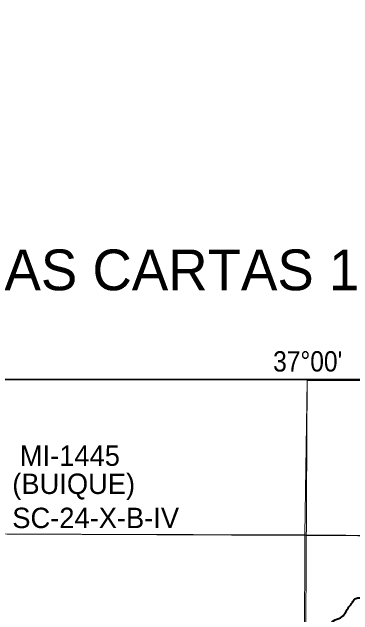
# Model space of a CAD drawing. Extents: x -1643653 to 4543381, y 1624270 to 13878484.
# Drawn here: x 600426 to 608778, y 8918990 to 8933785 of the extents above; entities that cross this region are included whole.
import ezdxf
from ezdxf.enums import TextEntityAlignment as Align

# ---------------------------------------------------------------- set-up
doc = ezdxf.new("R2010")
doc.units = 0
doc.header["$LTSCALE"] = 160
doc.layers.add('6', color=7, linetype='Continuous', lineweight=13)
doc.layers.add('60', color=7, linetype='Continuous', lineweight=13)

msp = doc.modelspace()

# ---------------------------------------------------------------- linework, layer by layer
at = {"layer": '6', "lineweight": 35}
msp.add_lwpolyline([(574695.3, 8924769.6), (626625.7, 8924769.6), (626625.7, 8896026.7), (574695.3, 8896026.7)], close=True, dxfattribs=at)
at = {"layer": '6'}
for points in [[(607657.7, 8924743.3), (607574.2, 8909874.9), (607492.3, 8896026.7)], [(574684.9, 8921064.7), (596639.8, 8920989.8), (607636.3, 8920937.2), (626625.7, 8920820.5)], [(608653.2, 8919135.4), (608627.5, 8919108.1), (608598.7, 8919080.5), (608588.5, 8919064.1), (608579.3, 8919042.5), (608574.7, 8919033.7)]]:
    msp.add_lwpolyline(points, dxfattribs=at)
for points in [[(607657.7, 8924743.3), (618663, 8924716.1), (618636, 8920869.6), (607600.8, 8920952.4)], [(607600.8, 8920952.4), (596639.8, 8920989.8), (596608.8, 8909934.4), (607569.8, 8909894.9)]]:
    msp.add_lwpolyline(points, close=True, dxfattribs=at)
at = {"layer": '6', "lineweight": 40}
msp.add_spline([(605233.4, 8918291.8), (605425.1, 8918291.8), (605556.8, 8918274.6), (605694.1, 8918217.3), (605780, 8918168.6), (605911.6, 8918165.8), (606008.9, 8918211.6), (606114.8, 8918211.6), (606197.8, 8918134.3), (606353.7, 8918138.6), (606551.2, 8918198.7), (606637.1, 8918198.7), (606903.2, 8918104.2), (607195.1, 8918130), (607418.3, 8918172.9), (607555.7, 8918130), (607658.7, 8918138.6), (607753.1, 8918172.9), (607813.2, 8918172.9), (607967.8, 8918353.3), (608139.5, 8918542.3), (608208.1, 8918748.4), (608345.5, 8918868.7), (608508.6, 8918946), (608680.3, 8919186.5), (608766.2, 8919298.2), (608826.3, 8919384.1), (608920.7, 8919409.8), (609058.1, 8919427), (609126.8, 8919444.2), (609186.8, 8919512.9), (609272.7, 8919538.7), (609418.7, 8919530.1), (609633.3, 8919581.6), (609805, 8919650.3), (609950.9, 8919727.6), (610174.2, 8919847.9), (610285.8, 8919890.8), (610500.4, 8919959.5), (610612, 8920002.5), (610715, 8920002.5), (610989.7, 8919925.2)], degree=3, dxfattribs=at)
at = {"layer": '60', "lineweight": 25}
msp.add_spline([(814781, 9009175.5), (814787.2, 9009173.4), (814796.9, 9009173.4), (814799.4, 9009172.4), (814805.1, 9009174.5), (814805.6, 9009176.5), (814811.7, 9009179.5), (814811.7, 9009179.5), (814801.5, 9009181), (814790.7, 9009181.5), (814784.1, 9009183.1), (814777.4, 9009185.1), (814778.4, 9009175.5)], degree=3, dxfattribs=at)

# ---------------------------------------------------------------- texts
at = {"layer": '6'}
msp.add_text('ARTICULAÇÃO DAS CARTAS 1:100.000', height=1000, dxfattribs=at).set_placement((601765.5, 8926958.2), align=Align.CENTER)
at = {"layer": '6', "width": 0.9}
msp.add_text("37°00'", height=500, dxfattribs=at).set_placement((607670.1, 8924963.2), align=Align.CENTER)
at = {"layer": '6'}
for s, p in [('MI-1445', (600615.8, 8922649.4)), ('(BUIQUE)', (600431.4, 8921958.8)), ('SC-24-X-B-IV', (600431.4, 8921121.7))]:
    msp.add_text(s, height=500, dxfattribs=at).set_placement(p)

doc.saveas('drawing.dxf')
